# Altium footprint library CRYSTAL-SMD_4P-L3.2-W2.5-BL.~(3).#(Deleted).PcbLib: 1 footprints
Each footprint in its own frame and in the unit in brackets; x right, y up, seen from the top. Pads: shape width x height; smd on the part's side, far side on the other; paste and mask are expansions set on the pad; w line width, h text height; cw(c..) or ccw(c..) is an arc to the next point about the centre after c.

## CRYSTAL-SMD_4P-L3.2-W2.5-BL [mm]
